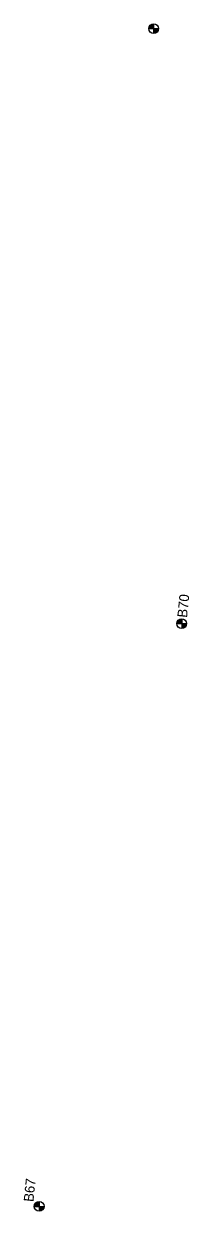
# Model space of a CAD drawing. Extents: x 345549 to 379569, y 127949 to 230467.
# Drawn here: x 359505 to 359673, y 167656 to 168862 of the extents above; entities that cross this region are included whole.
import ezdxf

# ---------------------------------------------------------------- set-up
doc = ezdxf.new("R2010")
doc.units = 0
doc.layers.add('E_SOIL_BORE1 [KAPUR_CADDS_LEVELS]', color=7, linetype='Continuous')
doc.layers.add('P_MARK', color=7, linetype='Continuous')

msp = doc.modelspace()

# ---------------------------------------------------------------- linework, layer by layer
at = {"layer": 'P_MARK'}
for p, q in [((359631.8, 168856.8), (359641.8, 168856.8)), ((359636.8, 168861.8), (359636.8, 168851.8)), ((359660.4, 168252.8), (359670.4, 168252.8)), ((359665.4, 168257.8), (359665.4, 168247.8)), ((359520.3, 167666.3), (359520.3, 167656.3)), ((359515.3, 167661.3), (359525.3, 167661.3))]:
    msp.add_line(p, q, dxfattribs=at)
for centre in [(359636.8, 168856.8), (359665.4, 168252.8), (359520.3, 167661.3)]:
    msp.add_circle(centre, 5, dxfattribs=at)
for centre, radius, start, end in [((359636.8, 168856.8), 4.5, 89.9869, 179.9869), ((359636.8, 168856.8), 4, 89.9869, 179.9869), ((359636.8, 168856.8), 3.5, 89.9869, 179.9869), ((359636.8, 168856.8), 3, 89.9869, 179.9869), ((359636.8, 168856.8), 2.5, 89.9869, 179.9869), ((359636.8, 168856.8), 2, 89.9869, 179.9869), ((359636.8, 168856.8), 1.5, 89.9869, 179.9869), ((359636.8, 168856.8), 1, 89.9869, 179.9869), ((359636.8, 168856.8), 0.5, 89.9869, 179.9869), ((359636.8, 168856.8), 4.5, 269.9869, 359.9869), ((359636.8, 168856.8), 4, 269.9869, 359.9869), ((359636.8, 168856.8), 3.5, 269.9869, 359.9869), ((359636.8, 168856.8), 3, 269.9869, 359.9869), ((359636.8, 168856.8), 2.5, 269.9869, 359.9869), ((359636.8, 168856.8), 2, 269.9869, 359.9869), ((359636.8, 168856.8), 1.5, 269.9869, 359.9869), ((359636.8, 168856.8), 1, 269.9869, 359.9869), ((359636.8, 168856.8), 0.5, 269.9869, 359.9869), ((359665.4, 168252.8), 4.5, 89.9869, 179.9869), ((359665.4, 168252.8), 4, 89.9869, 179.9869), ((359665.4, 168252.8), 3.5, 89.9869, 179.9869), ((359665.4, 168252.8), 3, 89.9869, 179.9869), ((359665.4, 168252.8), 2.5, 89.9869, 179.9869), ((359665.4, 168252.8), 2, 89.9869, 179.9869), ((359665.4, 168252.8), 1.5, 89.9869, 179.9869), ((359665.4, 168252.8), 1, 89.9869, 179.9869), ((359665.4, 168252.8), 0.5, 89.9869, 179.9869), ((359665.4, 168252.8), 4.5, 269.9869, 359.9869), ((359665.4, 168252.8), 4, 269.9869, 359.9869), ((359665.4, 168252.8), 3.5, 269.9869, 359.9869), ((359665.4, 168252.8), 3, 269.9869, 359.9869), ((359665.4, 168252.8), 2.5, 269.9869, 359.9869), ((359665.4, 168252.8), 2, 269.9869, 359.9869), ((359665.4, 168252.8), 1.5, 269.9869, 359.9869), ((359665.4, 168252.8), 1, 269.9869, 359.9869), ((359665.4, 168252.8), 0.5, 269.9869, 359.9869), ((359520.3, 167661.3), 4.5, 89.9869, 179.9869), ((359520.3, 167661.3), 4, 89.9869, 179.9869), ((359520.3, 167661.3), 3.5, 89.9869, 179.9869), ((359520.3, 167661.3), 3, 89.9869, 179.9869), ((359520.3, 167661.3), 2.5, 89.9869, 179.9869), ((359520.3, 167661.3), 2, 89.9869, 179.9869), ((359520.3, 167661.3), 1.5, 89.9869, 179.9869), ((359520.3, 167661.3), 1, 89.9869, 179.9869), ((359520.3, 167661.3), 0.5, 89.9869, 179.9869), ((359520.3, 167661.3), 4.5, 269.9869, 359.9869), ((359520.3, 167661.3), 4, 269.9869, 359.9869), ((359520.3, 167661.3), 3.5, 269.9869, 359.9869), ((359520.3, 167661.3), 3, 269.9869, 359.9869), ((359520.3, 167661.3), 2.5, 269.9869, 359.9869), ((359520.3, 167661.3), 2, 269.9869, 359.9869), ((359520.3, 167661.3), 1.5, 269.9869, 359.9869), ((359520.3, 167661.3), 1, 269.9869, 359.9869), ((359520.3, 167661.3), 0.5, 269.9869, 359.9869)]:
    msp.add_arc(centre, radius, start, end, dxfattribs=at)

# ---------------------------------------------------------------- texts
at = {"layer": 'E_SOIL_BORE1 [KAPUR_CADDS_LEVELS]'}
for s, p in [('B70', (359670.8, 168258.5)), ('B67', (359514.4, 167665.5))]:
    msp.add_text(s, height=10, rotation=84.1728, dxfattribs=at).set_placement(p)

doc.saveas('drawing.dxf')
